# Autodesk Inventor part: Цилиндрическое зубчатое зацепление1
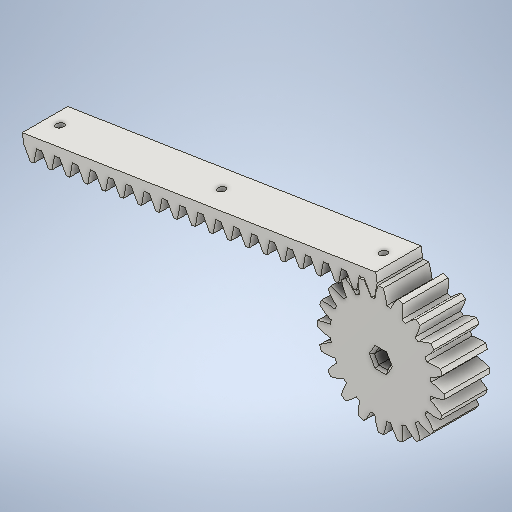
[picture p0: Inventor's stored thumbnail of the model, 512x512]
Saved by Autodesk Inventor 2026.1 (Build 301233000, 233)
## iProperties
CustomPartVersion: 1
Created: 2026-01
Part Number: Цилиндрическое зубчатое зацепление1
Material: Steel
Document SubType Name: Modeling
Designer: Yury Melnikov
Categories: <?xml version="1.0" encoding="UTF-16"?> <MemberInstance><Categories><FamilyTemplate><FamilyTemplateParameter ValueType="xs:double" Id="1" ObjectReferenceKey="da
Density: 1 g/cm^3
Appearance: Steel
Author: Yury Melnikov
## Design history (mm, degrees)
sketch "Sketch1"
  geometry: C1 r 21.01 at (0, 0)
  constraints: 1 centre point
  dimensions: "d0" = 42.02 diameter of C1 (= da_da)
extrude "Extrusion1" new body sketch "Sketch1" distance "d1" = 15 (= da_b); taper "d2" = 0 deg
workplane "Work Plane2"
feature "Средний диаметр" dims "d4" = 10, "d5" = 0
workplane "Work Plane8"
workplane "Work Plane9"
feature "Цилиндрическое зубчатое зацепление" dims "da_b" = 15, "da_d" = 38.2, "da_aw" = 73.535, "da_da" = 42.02, "da_df" = 33.425, "da_dw" = 38.2, angle "da_beta" = 0 deg, "da_lefttooth" = 0, "da_righttooth" = 0
sketch "Эскиз3"
  geometry: L1 (-5.461, 20.743)-(-3.244, 16.743); L2 (-3.244, 16.743)-(-2.089, 16.926); L3 (-2.089, 16.926)-(-1.216, 21.415); L4 (-1.216, 21.415)-(-5.461, 20.743); L5 (-5.703, 20.221)-(-0.825, 20.994); L6 (-3.339, 21.079)-(-3.264, 20.607); L7 (-118.08, 2.906)-(-1.216, 21.415); L8 (-1.216, 21.415)-(-1.686, 24.378); L9 (-1.686, 24.378)-(-118.55, 5.869); L10 (-118.55, 5.869)-(-118.08, 2.906); L11 (-11.388, 19.804)-(-9.171, 15.804); L12 (-9.171, 15.804)-(-8.016, 15.987); L13 (-11.63, 19.282)-(-6.752, 20.055); L14 (-8.016, 15.987)-(-7.144, 20.476); L15 (-17.316, 18.865)-(-15.098, 14.865); L16 (-15.098, 14.865)-(-13.944, 15.048); L17 (-17.558, 18.344)-(-12.68, 19.116); L18 (-13.944, 15.048)-(-13.071, 19.538); L19 (-23.243, 17.927)-(-21.026, 13.927); L20 (-21.026, 13.927)-(-19.871, 14.11); L21 (-23.485, 17.405)-(-18.607, 18.177); L22 (-19.871, 14.11)-(-18.998, 18.599); L23 (-29.17, 16.988)-(-26.953, 12.988); L24 (-26.953, 12.988)-(-25.798, 13.171); L25 (-29.412, 16.466)-(-24.534, 17.239); L26 (-25.798, 13.171)-(-24.926, 17.66); L27 (-35.098, 16.049)-(-32.88, 12.049); L28 (-32.88, 12.049)-(-31.726, 12.232); L29 (-35.34, 15.527)-(-30.462, 16.3); L30 (-31.726, 12.232)-(-30.853, 16.721); L31 (-41.025, 15.11)-(-38.808, 11.11); L32 (-38.808, 11.11)-(-37.653, 11.293); L33 (-41.267, 14.588)-(-36.389, 15.361); L34 (-37.653, 11.293)-(-36.78, 15.782); L35 (-46.952, 14.171)-(-44.735, 10.171); L36 (-44.735, 10.171)-(-43.58, 10.354); L37 (-47.194, 13.65)-(-42.316, 14.422); L38 (-43.58, 10.354)-(-42.708, 14.844); L39 (-52.88, 13.233)-(-50.662, 9.233); L40 (-50.662, 9.233)-(-49.508, 9.416); L41 (-53.122, 12.711)-(-48.244, 13.483); L42 (-49.508, 9.416)-(-48.635, 13.905); L43 (-58.807, 12.294)-(-56.59, 8.294); L44 (-56.59, 8.294)-(-55.435, 8.477); L45 (-59.049, 11.772)-(-54.171, 12.545); L46 (-55.435, 8.477)-(-54.562, 12.966); L47 (-64.734, 11.355)-(-62.517, 7.355); L48 (-62.517, 7.355)-(-61.362, 7.538); L49 (-64.976, 10.833)-(-60.098, 11.606); L50 (-61.362, 7.538)-(-60.49, 12.027); L51 (-70.662, 10.416)-(-68.444, 6.416); L52 (-68.444, 6.416)-(-67.29, 6.599); L53 (-70.904, 9.894)-(-66.026, 10.667); L54 (-67.29, 6.599)-(-66.417, 11.088); L55 (-76.589, 9.477)-(-74.372, 5.478); L56 (-74.372, 5.478)-(-73.217, 5.66); L57 (-76.831, 8.956)-(-71.953, 9.728); L58 (-73.217, 5.66)-(-72.344, 10.15); L59 (-82.516, 8.539)-(-80.299, 4.539); L60 (-80.299, 4.539)-(-79.144, 4.722); L61 (-82.758, 8.017)-(-77.88, 8.789); L62 (-79.144, 4.722)-(-78.272, 9.211); L63 (-88.444, 7.6)-(-86.226, 3.6); L64 (-86.226, 3.6)-(-85.072, 3.783)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; C1 r 19.1 at (0, 0); A1 r 21.01 centre (0, 0) between (-5.703, 20.221) and (-7.272, 19.711) reference; A2 r 15.832 centre (13.773, 14.865) between (-0.825, 20.994) and (-1.964, 16.597) reference; 58 further points
  constraints: 210 end point, 4 parallel, 3 coincident, 2 midpoint, 2 perpendicular, 1 centre point, 1 collinear, 1 equal length, 265 other
  dimensions: "d49" = 38.2 diameter of C1; "d50" = 70 deg angle of L3 L4; "d51" = 4.2975 distance between parallel lines of L2 L4; "d52" = 0.4775 distance between parallel lines of L5 L4; "d55" = 4.2975 distance of L3.end L1.start; "d56" = 3 distance of L3.end L8.end; "d59" = 6.00122 distance of L1.start L11.start; "d76" = 6.00122 distance of L1.start L88.start (derived)
extrude "Выдавливание2" new body sketch "Эскиз3" distance "d71" = 15; taper "d72" = 0 deg
sketch "Эскиз4"
  geometry: L1 (-2.565, 7.5)-(51.595, 7.5); L2 (51.595, 7.5)-(105.755, 7.5); L3 (-7.565, 15)-(-7.565, 0) reference; L4 (110.755, 15)-(110.755, 0) reference; C1 r 1.25 at (-2.565, 7.5); C2 r 1.25 at (51.595, 7.5); C3 r 1.25 at (105.755, 7.5); 3 further points
  constraints: 4 end point, 3 centre point, 2 collinear, 2 equal radius, 2 midpoint, 1 horizontal, 1 horizontal alignment
  dimensions: "d81" = 5 distance from line of L2.end L4; "d82" = 5 distance of L1.start point (-7.565, 7.5); "d83" = 2.5 diameter of C3
extrude "Выдавливание3" cut sketch "Эскиз4" distance "d84" = 10; taper "d85" = 0 deg
node "РабПлоскость11"
sketch "Эскиз5"
  geometry: L1 (-26.738, 0)-(-26.738, 15) reference; C1 r 1.25 at (-5, 7.5) reference; C2 r 1.25 at (-59.16, 7.5) reference; C3 r 1.25 at (-113.321, 7.5) reference; C4 r 2.6 at (-113.321, 7.5); C5 r 2.6 at (-59.16, 7.5); C6 r 2.6 at (-5, 7.5); 1 further point
  constraints: 3 centre point, 2 equal radius
  dimensions: "d87" = 5.2 diameter of C6
extrude "Выдавливание4" cut sketch "Эскиз5" distance "d88" = 35.95; taper "d89" = 0 deg
chamfer "Фаска1" distance "d90" = 1; stored, may be unused: second distance "d91" = 2, angle "d92" = 45 deg
sketch "Эскиз6"
  geometry: L1 (-1.443, 2.5)-(1.443, 2.5); L2 (1.443, 2.5)-(2.887, 0); L3 (2.887, 0)-(1.443, -2.5); L4 (1.443, -2.5)-(-1.443, -2.5); L5 (-1.443, -2.5)-(-2.887, 0); L6 (-2.887, 0)-(-1.443, 2.5); 2 further points
  constraints: 12 end point, 1 coincident, 1 horizontal, 13 other
  dimensions: "d93" = 5 distance between parallel lines of L4 L1
extrude "Выдавливание5" cut sketch "Эскиз6" distance "d94" = 35.95; taper "d95" = 0 deg
chamfer "Фаска2" distance "d96" = 0.8; stored, may be unused: second distance "d97" = 2, angle "d98" = 45 deg
feature "֦耀֨耀֪耀֬耀֮耀ְ耀ֲ耀ִ耀" dims "d0" = 42.02 (= da_da), "d1" = 15 (= da_b), "d2" = 0, "d3" = 38.2 (= da_d), "d4" = 10, "d5" = 0, "d16" = 73.535 (= da_aw), "d17" = 0, "d34" = 9 deg (computed from da_z), "d39" = 0, "d41" = 0, "d43" = 73.535 (= da_aw), "d46" = 73.535 (= da_aw), "d47" = 0, "d48" = 0, "d49" = 38.2, "d50" = 70 deg, "d51" = 4.2975, "d52" = 0.4775, "d55" = 4.2975, "d56" = 3, "d57" = 200 (= Z), "d59" = 6.00122, "d60" = 10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
body "Solid1"
sketch "Sketch2"
  geometry: C1 r 21.01 at (0, 0) reference; C2 r 19.1 at (0, 0)
  constraints: 1 centre point, 1 coincident
  dimensions: "d3" = 38.2 diameter of C2 (= da_d)
body "Srf1"
node "Эскиз — прямоугольный массив1" dims "d59" = 6.00122, "d62" = 10
node "Эскиз — прямоугольный массив3" dims "d76" = 6.00122 (derived), "d79" = 10
node "Твердое тело2"
